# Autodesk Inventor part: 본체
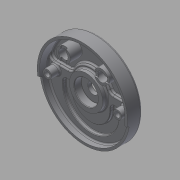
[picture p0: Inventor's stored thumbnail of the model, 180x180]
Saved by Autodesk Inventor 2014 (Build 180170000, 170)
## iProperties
Created: 2015-06
Part Number: 본체
Material: Generic
Document SubType Name: Modeling
Designer: MYHOME
Density: 1 g/cm^3
Appearance: Default
Author: MYHOME
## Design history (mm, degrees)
sketch "스케치1"
  geometry: C1 r 95 at (0, 0); 1 further point
  constraints: 1 centre point, 1 coincident
  dimensions: "d0" = 190 diameter of C1
extrude "돌출1" new body sketch "스케치1" distance "d1" = 32; taper "d2" = 0 deg
sketch "스케치2"
  geometry: C1 r 95 at (0, 0) reference; C2 r 90 at (0, 0)
  constraints: 1 centre point, 1 coincident
  dimensions: "d3" = 180 diameter of C2
extrude "돌출2" cut sketch "스케치2" distance "d4" = 25; taper "d5" = 0 deg
sketch "스케치4"
  geometry: L1 (0, 0)-(-95, 0); L2 (0, 0)-(-94.075, -13.221); L3 (0, 0)-(95, 0); L4 (0, 0)-(94.075, -13.221); A1 r 95 centre (0, 0) between (-95, 0) and (-94.075, -13.221) reference
  constraints: 8 end point, 4 point on circle, 1 collinear, 1 horizontal
  dimensions: "d6" = 8 deg angle of L1 L2; "d7" = 8 deg angle of L4 L3
extrude "돌출3" cut sketch "스케치4" distance "d8" = 5; taper "d9" = 0 deg
sketch "스케치6"
  geometry: L1 (-89.196, 12)-(-40.249, 12); L2 (40.249, 12)-(89.196, 12); A1 r 90 centre (0, 0) between (-89.196, 12) and (89.196, 12) reference; A2 r 42 centre (0, 0) between (40.249, 12) and (-40.249, 12)
  constraints: 4 end point, 4 point on circle, 2 horizontal, 1 centre point, 1 coincident, 1 collinear
  dimensions: "d15" = 42 radius of A2; "d17" = 12 distance from line of A1.centre L2
extrude "돌출4" join sketch "스케치6" distance "d18" = 7; taper "d19" = 0 deg
fillet "모깎기1" dims "d20" = 10
sketch "스케치7"
  geometry: C1 r 15 at (-40, 52); A1 r 90 centre (0, 0) between (86.53, 24.75) and (-86.53, 24.75) reference
  constraints: 1 centre point
  dimensions: "d21" = 30 diameter of C1; "d22" = 40 horizontal distance of A1.centre C1.centre; "d23" = 52 vertical distance of A1.centre C1.centre
extrude "돌출5" join sketch "스케치7" distance "d24" = 25; taper "d25" = 0 deg
sketch "스케치8"
  geometry: C1 r 15 at (0, 0) reference; C2 r 10 at (0, 0); 1 further point
  constraints: 1 centre point, 1 coincident
  dimensions: "d26" = 20 diameter of C2
extrude "돌출6" cut sketch "스케치8" stored distance "d27" = 25; taper "d28" = 0 deg
sketch "스케치9"
  geometry: L1 (-6, 15)-(6, 15); L2 (6, 15)-(6, -15); L3 (6, -15)-(-6, -15); L4 (-6, -15)-(-6, 15); C1 r 10 at (0, 0) reference; C2 r 15 at (0, 0) reference; 2 further points
  constraints: 8 end point, 2 parallel, 2 tangent, 1 horizontal, 1 midpoint, 1 perpendicular, 1 vertical alignment
  dimensions: "d29" = 12 distance of L2.end L3.end
extrude "돌출7" cut sketch "스케치9" distance "d31" = 3; taper "d32" = 0 deg
sketch "스케치10"
  geometry: L1 (-47.117, 12)-(-76.916, 12) reference; L2 (-50, -14)-(-50, -24); L3 (-41, -14)-(-41, -19); L4 (-59, -19)-(-59, -14); L5 (50, -14)-(50, -24); L6 (41, -14)-(41, -19); L7 (59, -19)-(59, -14); A1 r 90 centre (0, 0) between (-86.53, 24.75) and (86.53, 24.75) reference; A2 r 50 centre (0, -19) between (-50, -19) and (50, -19); A3 r 59 centre (0, -19) between (-59, -19) and (59, -19); A4 r 41 centre (0, -19) between (-41, -19) and (41, -19); A5 r 9 centre (-50, -19) between (-41, -19) and (-59, -19); A6 r 9 centre (50, -19) between (59, -19) and (41, -19); A7 r 9 centre (-50, -14) between (-41, -14) and (-59, -14); A8 r 9 centre (50, -14) between (59, -14) and (41, -14); 2 further points
  constraints: 16 end point, 14 point on circle, 8 tangent, 7 centre point, 3 parallel, 2 coincident, 2 horizontal alignment, 2 midpoint, 1 perpendicular, 1 vertical alignment
  dimensions: "d34" = 18 diameter of A6; "d35" = 59 radius of A3; "d36" = 19 distance of A2.centre A1.centre; "d38" = 5 distance of L2.start point (-50, -19); "d41" = 5 distance of L5.start point (50, -19)
extrude "돌출8" cut sketch "스케치10" distance "d42" = 7; taper "d43" = 0 deg
chamfer "모따기1" distance "d44" = 1; stored, may be unused: second distance "d45" = 2, angle "d46" = 45 deg
fillet "모깎기2" dims "d47" = 1
sketch "스케치11"
  geometry: C1 r 35 at (0, 0); A1 r 42 centre (0, 0) between (38.056, 17.769) and (-38.056, 17.769) reference
  constraints: 1 centre point, 1 coincident
  dimensions: "d48" = 70 diameter of C1
extrude "돌출9" join sketch "스케치11" distance "d49" = 10; taper "d50" = 0 deg
fillet "모깎기3" dims "d51" = 3
hole "구멍1" diameter "d54" = 23; stored, may be unused: countersink angle "d58" = 90 deg, drill point angle "d60" = 118 deg; dims "d52" = 10, "d53" = 10, "d55" = 6, "d56" = 50, "d57" = 15, "d59" = 8
chamfer "모따기2" distance "d61" = 1; stored, may be unused: second distance "d62" = 2, angle "d63" = 45 deg
fillet "모깎기4" dims "d64" = 0.3
sketch "스케치12"
  geometry: C1 r 9 at (-74, 0); A1 r 90 centre (0, 0) between (-86.53, 24.75) and (86.53, 24.75) reference
  constraints: 1 centre point, 1 horizontal alignment
  dimensions: "d65" = 18 diameter of C1; "d66" = 74 distance of A1.centre C1.centre
extrude "돌출10" join sketch "스케치12" stored distance "d67" = 10; taper "d68" = 0 deg
fillet "모깎기5" dims "d69" = 3
sketch "스케치13"
  geometry: L1 (-15, 6)-(15, 6); L2 (15, 6)-(15, -6); L3 (15, -6)-(-15, -6); L4 (-15, -6)-(-15, 6); C1 r 10 at (0, 0) reference; C2 r 15 at (0, 0) reference; 2 further points
  constraints: 8 end point, 2 parallel, 2 tangent, 1 horizontal, 1 horizontal alignment, 1 midpoint, 1 perpendicular
  dimensions: "d70" = 12 distance of L1.end L2.end
extrude "돌출11" cut sketch "스케치13" distance "d71" = 3; taper "d72" = 0 deg
sketch "스케치16"
  geometry: C1 r 9 at (74, 0) reference; C2 r 9 at (-74, 0) reference; 2 further points
  constraints: 2 coincident
hole "구멍2" sketch "스케치16" at (74, 0), (-74, 0) diameter "d73" = 11; stored, may be unused: countersink angle "d77" = 90 deg, drill point angle "d79" = 118 deg; dims "d74" = 6, "d75" = 18, "d76" = 11, "d78" = 8
fillet "모깎기6" dims "d80" = 3
fillet "모깎기7" dims "d81" = 3
fillet "모깎기8" dims "d82" = 5
fillet "모깎기9" dims "d83" = 3
sketch "스케치17"
  geometry: C1 r 90 at (0, 0) reference; C2 r 68 at (0, 0)
  constraints: 1 centre point, 1 coincident, 1 other
  dimensions: "d84" = 136 diameter of C2
feature "엠보싱1" sketch "스케치17" dims "d85" = 0.5, "d86" = 0
node "솔리드1"
mirror "대칭1"
mirror "대칭3"
node "투영된 루프1"
node "투영된 루프2"
other parameters: "d16" = 12
